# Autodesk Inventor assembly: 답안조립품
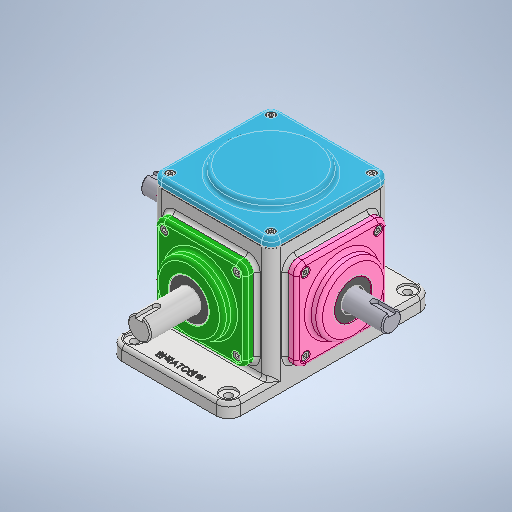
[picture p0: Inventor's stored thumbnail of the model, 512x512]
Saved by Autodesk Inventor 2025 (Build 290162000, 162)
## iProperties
Created: 2024-08
Part Number: 답안조립품
Document SubType Name: Assembly
Designer: rese9
Mass: 2752.21 g
Surface Area: 2659.3 cm^2
Volume: 867.108 cm^3
Density: 3.17402 g/cm^3
Author: rese9
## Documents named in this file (15)
- C:\Users\rese9\OneDrive\바탕 화면\640807V1010\답안조립품.iam
- C:\Users\rese9\OneDrive\바탕 화면\640807V1010\본체\본체.ipt
- C:\Users\rese9\OneDrive\바탕 화면\640807V1010\개스킷\개스킷.ipt
- C:\Users\rese9\OneDrive\바탕 화면\640807V1010\메인베벨기어\메인베벨기어.ipt
- C:\Users\rese9\OneDrive\바탕 화면\640807V1010\메인축\메인축.ipt
- C:\Users\rese9\OneDrive\바탕 화면\640807V1010\메인커버\메인커버.ipt
- C:\Users\rese9\OneDrive\바탕 화면\640807V1010\베어링 6203\베어링 6203.ipt
- C:\Users\rese9\OneDrive\바탕 화면\640807V1010\베어링 6204\베어링 6204.ipt
- C:\Users\rese9\OneDrive\바탕 화면\640807V1010\볼트 M4\볼트 M4.ipt
- C:\Users\rese9\OneDrive\바탕 화면\640807V1010\상부커버\상부커버.ipt
- C:\Users\rese9\OneDrive\바탕 화면\640807V1010\서브베벨기어\서브베벨기어.ipt
- C:\Users\rese9\OneDrive\바탕 화면\640807V1010\서브축\서브축.ipt
- C:\Users\rese9\OneDrive\바탕 화면\640807V1010\서브커버\서브커버.ipt
- C:\Users\rese9\OneDrive\바탕 화면\640807V1010\오일 실 20 35 8\오일 실 20 35 8.ipt
- C:\Users\rese9\OneDrive\바탕 화면\640807V1010\키 4x4\키 4x4.ipt
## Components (1 placed, 1 different names)
1. 개스킷:1
## Named parameters: d13_d0 = 0, d14_d1 = 0, d15_d2 = 0, d16_d3 = 0, d17_d6 = 0, d18_d7 = 0, d19_d8 = 180 deg
